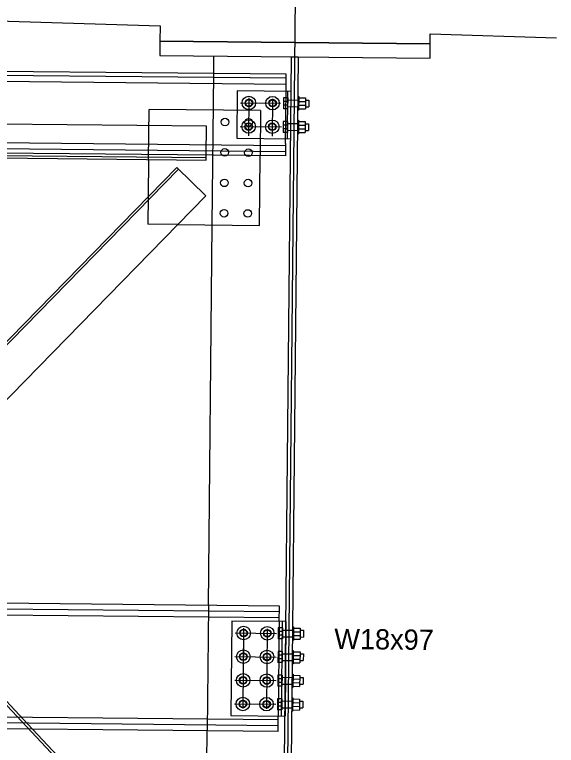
# Model space of a CAD drawing. Extents: x 632312 to 632425, y 378332 to 378413.
# Drawn here: x 632401.1 to 632407.78, y 378386.51 to 378395.52 of the extents above; entities that cross this region are included whole.
import ezdxf

# ---------------------------------------------------------------- set-up
doc = ezdxf.new("R2010")
doc.units = 0
for name, color, linetype in [('B_Boring', 7, 'Continuous'), ('B_Boring Annot', 7, 'Continuous'), ('R_Proposed Const Limits Cut', 7, 'Continuous'), ('R_Shade Removal', 7, 'Continuous'), ('R_Wall', 7, 'Continuous'), ('SHT_Dimensions', 7, 'Continuous')]:
    doc.layers.add(name, color=color, linetype=linetype)

msp = doc.modelspace()

# ---------------------------------------------------------------- linework, layer by layer
at = {"layer": 'B_Boring'}
for p, q in [((632403.5554, 378394.7968), (632403.5576, 378395.0114)), ((632404.4507, 378394.7374), (632393.4096, 378394.8472)), ((632404.4512, 378394.7879), (632393.4101, 378394.8976)), ((632404.4494, 378394.5995), (632404.4512, 378394.7879)), ((632403.845, 378394.5814), (632403.8392, 378393.9981)), ((632404.5116, 378394.5748), (632403.845, 378394.5814)), ((632404.4642, 378393.9919), (632404.47, 378394.5752)), ((632404.4171, 378394.4976), (632404.4158, 378394.3622)), ((632404.4692, 378394.497), (632404.4171, 378394.4976)), ((632404.4692, 378394.497), (632404.4678, 378394.3617)), ((632404.5943, 378394.5114), (632404.5927, 378394.3448)), ((632404.5943, 378394.5114), (632404.6047, 378394.5113)), ((632404.6047, 378394.5113), (632404.6031, 378394.3447)), ((632404.6046, 378394.4957), (632404.6879, 378394.4949)), ((632404.6879, 378394.4949), (632404.6866, 378394.3595)), ((632404.4683, 378394.4068), (632404.4162, 378394.4073)), ((632404.4687, 378394.4519), (632404.4167, 378394.4524)), ((632404.6037, 378394.4054), (632404.687, 378394.4046)), ((632404.6041, 378394.4506), (632404.6875, 378394.4497)), ((632404.6877, 378394.4688), (632404.7293, 378394.4684)), ((632404.7293, 378394.4684), (632404.7285, 378394.3851)), ((632402.7593, 378394.3526), (632402.7593, 378394.3526)), ((632404.4678, 378394.3617), (632404.4158, 378394.3622)), ((632404.5927, 378394.3448), (632404.6031, 378394.3447)), ((632404.6032, 378394.3603), (632404.6866, 378394.3595)), ((632404.6868, 378394.3855), (632404.7285, 378394.3851)), ((632404.5914, 378394.2198), (632404.5898, 378394.0531)), ((632404.5914, 378394.2198), (632404.6018, 378394.2197)), ((632404.6018, 378394.2197), (632404.6002, 378394.053)), ((632404.4142, 378394.2059), (632404.4129, 378394.0705)), ((632404.4658, 378394.1603), (632404.4138, 378394.1608)), ((632404.4663, 378394.2054), (632404.4142, 378394.2059)), ((632404.4663, 378394.2054), (632404.4649, 378394.07)), ((632404.6012, 378394.1589), (632404.6846, 378394.1581)), ((632404.6017, 378394.204), (632404.685, 378394.2032)), ((632404.685, 378394.2032), (632404.6837, 378394.0678)), ((632404.6848, 378394.1772), (632404.7264, 378394.1768)), ((632404.7264, 378394.1768), (632404.7256, 378394.0934)), ((632404.4649, 378394.07), (632404.4129, 378394.0705)), ((632404.4654, 378394.1151), (632404.4133, 378394.1156)), ((632404.5898, 378394.0531), (632404.6002, 378394.053)), ((632404.6003, 378394.0687), (632404.6837, 378394.0678)), ((632404.6008, 378394.1138), (632404.6841, 378394.113)), ((632404.6839, 378394.0939), (632404.7256, 378394.0934)), ((632403.8392, 378393.9981), (632404.5058, 378393.9915)), ((632404.4412, 378393.7796), (632393.4001, 378393.8893)), ((632404.4417, 378393.83), (632393.4006, 378393.9398)), ((632404.4427, 378393.9329), (632404.4412, 378393.7796)), ((632398.9201, 378393.7741), (632403.4615, 378393.7289)), ((632403.4615, 378393.7289), (632403.4621, 378393.7893)), ((632404.1202, 378392.9223), (632404.1287, 378393.7827)), ((632403.11, 378392.9324), (632404.1202, 378392.9223)), ((632403.4902, 378388.2341), (632403.5369, 378392.9281)), ((632404.3644, 378388.1529), (632393.365, 378388.2623)), ((632404.3652, 378388.2254), (632393.3657, 378388.3348)), ((632404.3633, 378388.0338), (632404.3652, 378388.2254)), ((632403.7799, 378388.0396), (632403.7683, 378386.873)), ((632404.4466, 378388.0329), (632403.7799, 378388.0396)), ((632404.3933, 378386.8668), (632404.4049, 378388.0334)), ((632404.3521, 378387.9558), (632404.3507, 378387.8204)), ((632404.4037, 378387.9101), (632404.3516, 378387.9106)), ((632404.4041, 378387.9552), (632404.3521, 378387.9558)), ((632404.5293, 378387.9696), (632404.5397, 378387.9695)), ((632404.5397, 378387.9695), (632404.538, 378387.8029)), ((632404.5391, 378387.9088), (632404.6224, 378387.9079)), ((632404.5396, 378387.9539), (632404.6229, 378387.9531)), ((632404.6229, 378387.9531), (632404.6215, 378387.8177)), ((632404.6226, 378387.927), (632404.6643, 378387.9266)), ((632404.6643, 378387.9266), (632404.6635, 378387.8433)), ((632404.4028, 378387.8198), (632404.3507, 378387.8204)), ((632404.4032, 378387.865), (632404.3512, 378387.8655)), ((632404.5382, 378387.8185), (632404.6215, 378387.8177)), ((632404.5387, 378387.8636), (632404.622, 378387.8628)), ((632404.6218, 378387.8437), (632404.6635, 378387.8433)), ((632404.5276, 378387.803), (632404.538, 378387.8029)), ((632404.3492, 378387.6641), (632404.3478, 378387.5287)), ((632404.4012, 378387.6636), (632404.3492, 378387.6641)), ((632404.5264, 378387.678), (632404.5368, 378387.6779)), ((632404.5368, 378387.6779), (632404.5351, 378387.5112)), ((632404.5367, 378387.6622), (632404.62, 378387.6614)), ((632404.62, 378387.6614), (632404.6186, 378387.526)), ((632404.6197, 378387.6354), (632404.6614, 378387.635)), ((632404.6614, 378387.635), (632404.6606, 378387.5516)), ((632404.4003, 378387.5733), (632404.3483, 378387.5738)), ((632404.4008, 378387.6185), (632404.3487, 378387.619)), ((632404.5358, 378387.572), (632404.6191, 378387.5711)), ((632404.5362, 378387.6171), (632404.6195, 378387.6163)), ((632404.6189, 378387.552), (632404.6606, 378387.5516)), ((632404.3999, 378387.5282), (632404.3478, 378387.5287)), ((632404.5247, 378387.5113), (632404.5351, 378387.5112)), ((632404.5353, 378387.5268), (632404.6186, 378387.526)), ((632404.3463, 378387.3724), (632404.3449, 378387.2371)), ((632404.3983, 378387.3719), (632404.3463, 378387.3724)), ((632404.5235, 378387.3863), (632404.5339, 378387.3862)), ((632404.5339, 378387.3862), (632404.5322, 378387.2196)), ((632404.5338, 378387.3706), (632404.6171, 378387.3698)), ((632404.6171, 378387.3698), (632404.6157, 378387.2344)), ((632404.3974, 378387.2817), (632404.3454, 378387.2822)), ((632404.3979, 378387.3268), (632404.3458, 378387.3273)), ((632404.5329, 378387.2803), (632404.6162, 378387.2795)), ((632404.5333, 378387.3255), (632404.6166, 378387.3246)), ((632404.6168, 378387.3437), (632404.6585, 378387.3433)), ((632404.6585, 378387.3433), (632404.6577, 378387.26)), ((632404.397, 378387.2365), (632404.3449, 378387.2371)), ((632404.5218, 378387.2197), (632404.5322, 378387.2196)), ((632404.5324, 378387.2352), (632404.6157, 378387.2344)), ((632404.616, 378387.2604), (632404.6577, 378387.26)), ((632404.5206, 378387.0947), (632404.531, 378387.0946)), ((632404.531, 378387.0946), (632404.5293, 378386.9279)), ((632404.3434, 378387.0808), (632404.342, 378386.9454)), ((632404.395, 378387.0351), (632404.3429, 378387.0357)), ((632404.3954, 378387.0803), (632404.3434, 378387.0808)), ((632404.5304, 378387.0338), (632404.6137, 378387.033)), ((632404.5309, 378387.0789), (632404.6142, 378387.0781)), ((632404.6142, 378387.0781), (632404.6128, 378386.9427)), ((632404.6139, 378387.0521), (632404.6556, 378387.0517)), ((632404.6556, 378387.0517), (632404.6548, 378386.9683)), ((632404.3941, 378386.9449), (632404.342, 378386.9454)), ((632404.3945, 378386.99), (632404.3425, 378386.9905)), ((632404.5189, 378386.928), (632404.5293, 378386.9279)), ((632404.5295, 378386.9435), (632404.6128, 378386.9427)), ((632404.53, 378386.9887), (632404.6133, 378386.9878)), ((632404.6131, 378386.9687), (632404.6548, 378386.9683)), ((632404.3505, 378386.748), (632393.351, 378386.8574)), ((632403.7683, 378386.873), (632404.435, 378386.8663)), ((632404.3497, 378386.6755), (632404.3517, 378386.8672)), ((632404.3497, 378386.6755), (632393.3503, 378386.7849)), ((632403.4569, 378384.8869), (632403.4748, 378386.6842))]:
    msp.add_line(p, q, dxfattribs=at)
for points in [[(632406.2241, 378394.9848), (632406.2259, 378395.1619), (632402.8927, 378395.1951), (632402.8909, 378395.018)], [(632404.4799, 378383.0016), (632404.3966, 378383.0024), (632404.5159, 378395.0018), (632404.5992, 378395.001)]]:
    msp.add_lwpolyline(points, close=True, dxfattribs=at)
for points in [[(632402.7532, 378393.736), (632402.7486, 378393.278)], [(632399.6797, 378389.4202), (632403.4571, 378393.2877), (632403.0994, 378393.6371), (632399.6748, 378390.1308)], [(632401.3225, 378386.7056), (632403.37, 378384.5241)]]:
    msp.add_lwpolyline(points, dxfattribs=at)
for centre in [(632403.9894, 378394.4341), (632404.281, 378394.4312), (632403.6953, 378394.1974), (632403.987, 378394.1945), (632403.9865, 378394.1425), (632404.2781, 378394.1396), (632403.6916, 378393.8225), (632403.9833, 378393.8196), (632403.6879, 378393.4475), (632403.9795, 378393.4446), (632403.6841, 378393.0725), (632403.9758, 378393.0696), (632403.9243, 378387.8923), (632404.216, 378387.8894), (632403.9214, 378387.6006), (632404.2131, 378387.5977), (632403.9185, 378387.309), (632404.2102, 378387.3061), (632403.9156, 378387.0173), (632404.2073, 378387.0144)]:
    msp.add_circle(centre, 0.0469, dxfattribs=at)
at = {"layer": 'B_Boring Annot'}
for p, q in [((632398.9372, 378395.5031), (632402.8946, 378395.3846)), ((632402.8946, 378395.3846), (632402.8927, 378395.1951)), ((632406.2259, 378395.1619), (632406.2271, 378395.2848)), ((632406.2271, 378395.2848), (632407.7817, 378395.2383)), ((632402.8927, 378395.1951), (632406.2259, 378395.1619))]:
    msp.add_line(p, q, dxfattribs=at)
at = {"layer": 'R_Proposed Const Limits Cut'}
for p, q in [((632404.45, 378394.6629), (632393.4089, 378394.7726)), ((632403.5369, 378392.9281), (632403.5554, 378394.7968)), ((632404.4427, 378393.9329), (632404.4494, 378394.5995)), ((632404.4689, 378394.471), (632404.5939, 378394.4698)), ((632402.7532, 378393.736), (632402.7593, 378394.3526)), ((632404.1343, 378394.3389), (632402.7593, 378394.3526)), ((632404.1343, 378394.3389), (632404.1287, 378393.7827)), ((632404.4681, 378394.3877), (632404.5931, 378394.3864)), ((632403.4656, 378394.1456), (632394.3828, 378394.2359)), ((632403.4621, 378393.7893), (632403.4656, 378394.1456)), ((632404.466, 378394.1794), (632404.591, 378394.1781)), ((632404.4652, 378394.096), (632404.5902, 378394.0948)), ((632404.4425, 378393.9046), (632393.4013, 378394.0143)), ((632403.4618, 378393.755), (632394.3789, 378393.8453)), ((632394.716, 378393.6988), (632403.3472, 378384.5027)), ((632403.1218, 378393.6153), (632394.3094, 378384.5926)), ((632402.7486, 378393.278), (632402.7452, 378392.936)), ((632403.11, 378392.9324), (632402.7452, 378392.936)), ((632399.8539, 378388.2703), (632401.3225, 378386.7056)), ((632404.3637, 378388.0796), (632393.3643, 378388.189)), ((632403.4902, 378388.2341), (632403.4748, 378386.6842)), ((632404.3633, 378388.0338), (632404.3517, 378386.8672)), ((632404.4039, 378387.9292), (632404.5289, 378387.928)), ((632404.4031, 378387.8459), (632404.528, 378387.8446)), ((632404.401, 378387.6375), (632404.526, 378387.6363)), ((632404.4002, 378387.5542), (632404.5251, 378387.553)), ((632404.3981, 378387.3459), (632404.5231, 378387.3447)), ((632404.3973, 378387.2626), (632404.5222, 378387.2613)), ((632404.3952, 378387.0542), (632404.5202, 378387.053)), ((632404.3512, 378386.8213), (632393.3517, 378386.9307)), ((632404.3944, 378386.9709), (632404.5193, 378386.9697))]:
    msp.add_line(p, q, dxfattribs=at)
for centre, radius in [((632403.9894, 378394.4341), 0.0833), ((632404.281, 378394.4312), 0.0833), ((632403.9894, 378394.4341), 0.0417), ((632404.281, 378394.4312), 0.0417), ((632403.9865, 378394.1425), 0.0833), ((632404.2781, 378394.1396), 0.0833), ((632403.9865, 378394.1425), 0.0417), ((632404.2781, 378394.1396), 0.0417), ((632403.9243, 378387.8923), 0.0833), ((632403.9243, 378387.8923), 0.0417), ((632404.216, 378387.8894), 0.0833), ((632404.216, 378387.8894), 0.0417), ((632403.9214, 378387.6006), 0.0833), ((632403.9214, 378387.6006), 0.0417), ((632404.2131, 378387.5977), 0.0833), ((632404.2131, 378387.5977), 0.0417), ((632403.9185, 378387.309), 0.0833), ((632404.2102, 378387.3061), 0.0833), ((632403.9185, 378387.309), 0.0417), ((632404.2102, 378387.3061), 0.0417), ((632403.9156, 378387.0173), 0.0833), ((632404.2073, 378387.0144), 0.0833), ((632403.9156, 378387.0173), 0.0417), ((632404.2073, 378387.0144), 0.0417)]:
    msp.add_circle(centre, radius, dxfattribs=at)
at = {"layer": 'R_Shade Removal'}
msp.add_line((632404.4265, 378381.825), (632404.5664, 378395.8972), dxfattribs=at)
at = {"layer": 'R_Wall'}
for p, q in [((632403.99, 378394.4946), (632403.9853, 378394.0297)), ((632404.2816, 378394.4854), (632404.277, 378394.0223)), ((632403.8852, 378394.4351), (632404.3798, 378394.4302)), ((632403.8823, 378394.1435), (632404.3921, 378394.1384)), ((632403.9249, 378387.9528), (632403.915, 378386.9595)), ((632404.2165, 378387.9436), (632404.2067, 378386.9583)), ((632403.8202, 378387.8933), (632404.33, 378387.8883)), ((632403.8173, 378387.6017), (632404.3271, 378387.5966)), ((632403.8144, 378387.31), (632404.3242, 378387.305)), ((632403.8115, 378387.0184), (632404.3213, 378387.0133))]:
    msp.add_line(p, q, dxfattribs=at)
at = {"layer": 'SHT_Dimensions'}
for p, q in [((632404.4466, 378388.0329), (632404.435, 378386.8663)), ((632403.9249, 378387.9528), (632403.9181, 378387.2627)), ((632404.4041, 378387.9552), (632404.4028, 378387.8198)), ((632404.4012, 378387.6636), (632404.3999, 378387.5282)), ((632404.3983, 378387.3719), (632404.397, 378387.2365)), ((632404.5235, 378387.3863), (632404.5218, 378387.2197)), ((632404.3954, 378387.0803), (632404.3941, 378386.9449))]:
    msp.add_line(p, q, dxfattribs=at)

# ---------------------------------------------------------------- texts
msp.add_text('W18x97', height=0.25, rotation=359.43036, dxfattribs=at).set_placement((632405.0426, 378387.6958))

doc.saveas('drawing.dxf')
